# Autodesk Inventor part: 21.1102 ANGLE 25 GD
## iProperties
Created: 2007-01
Part Number: 21.1102 ANGLE 25 GD
Document SubType Name: Modeling
Designer: Andy Moles
Material: Aluminum-6061
Density: 2.71 g/cm^3
Mass: 41.3209 g
Surface Area: 72.3088 cm^2
Volume: 15.2476 cm^3
Author: Andy Moles
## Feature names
1. Base1
